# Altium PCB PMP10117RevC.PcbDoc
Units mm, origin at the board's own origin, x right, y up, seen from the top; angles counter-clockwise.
Board outline 44.45 x 78.74 mm, 4 copper layers (Top Layer, Inner Layer 1, Inner Layer 2, Bottom Layer), stack 2.062 mm thick; 56 components, 27 nets, 138 pads, 110 vias.
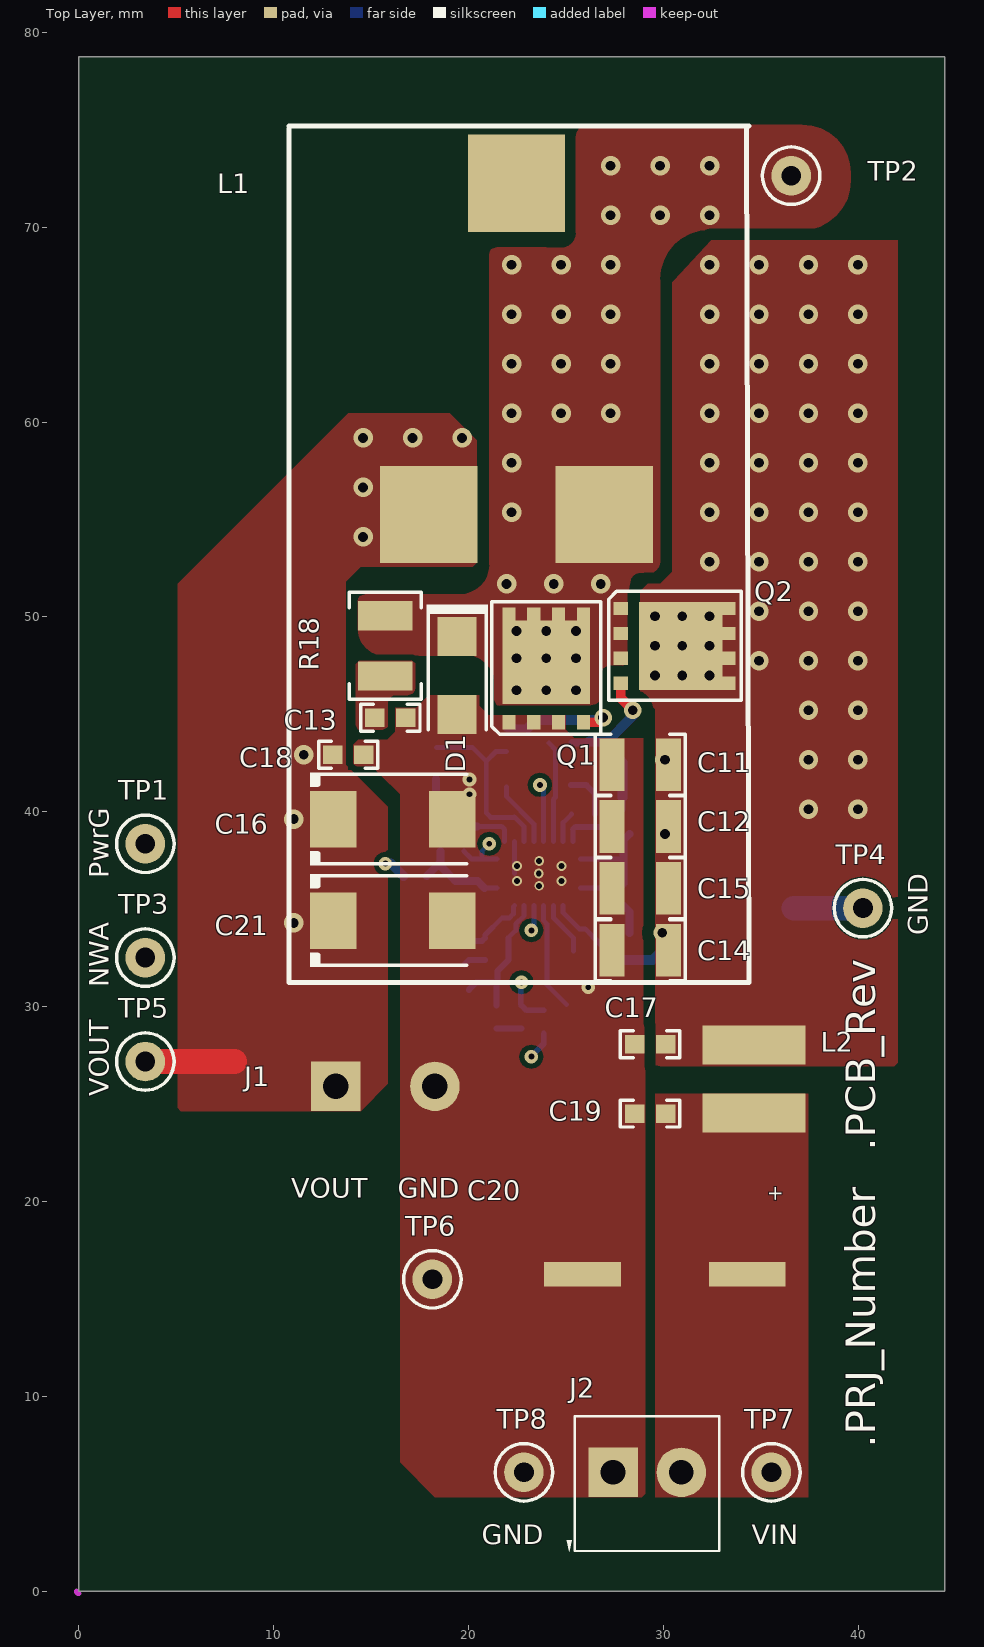
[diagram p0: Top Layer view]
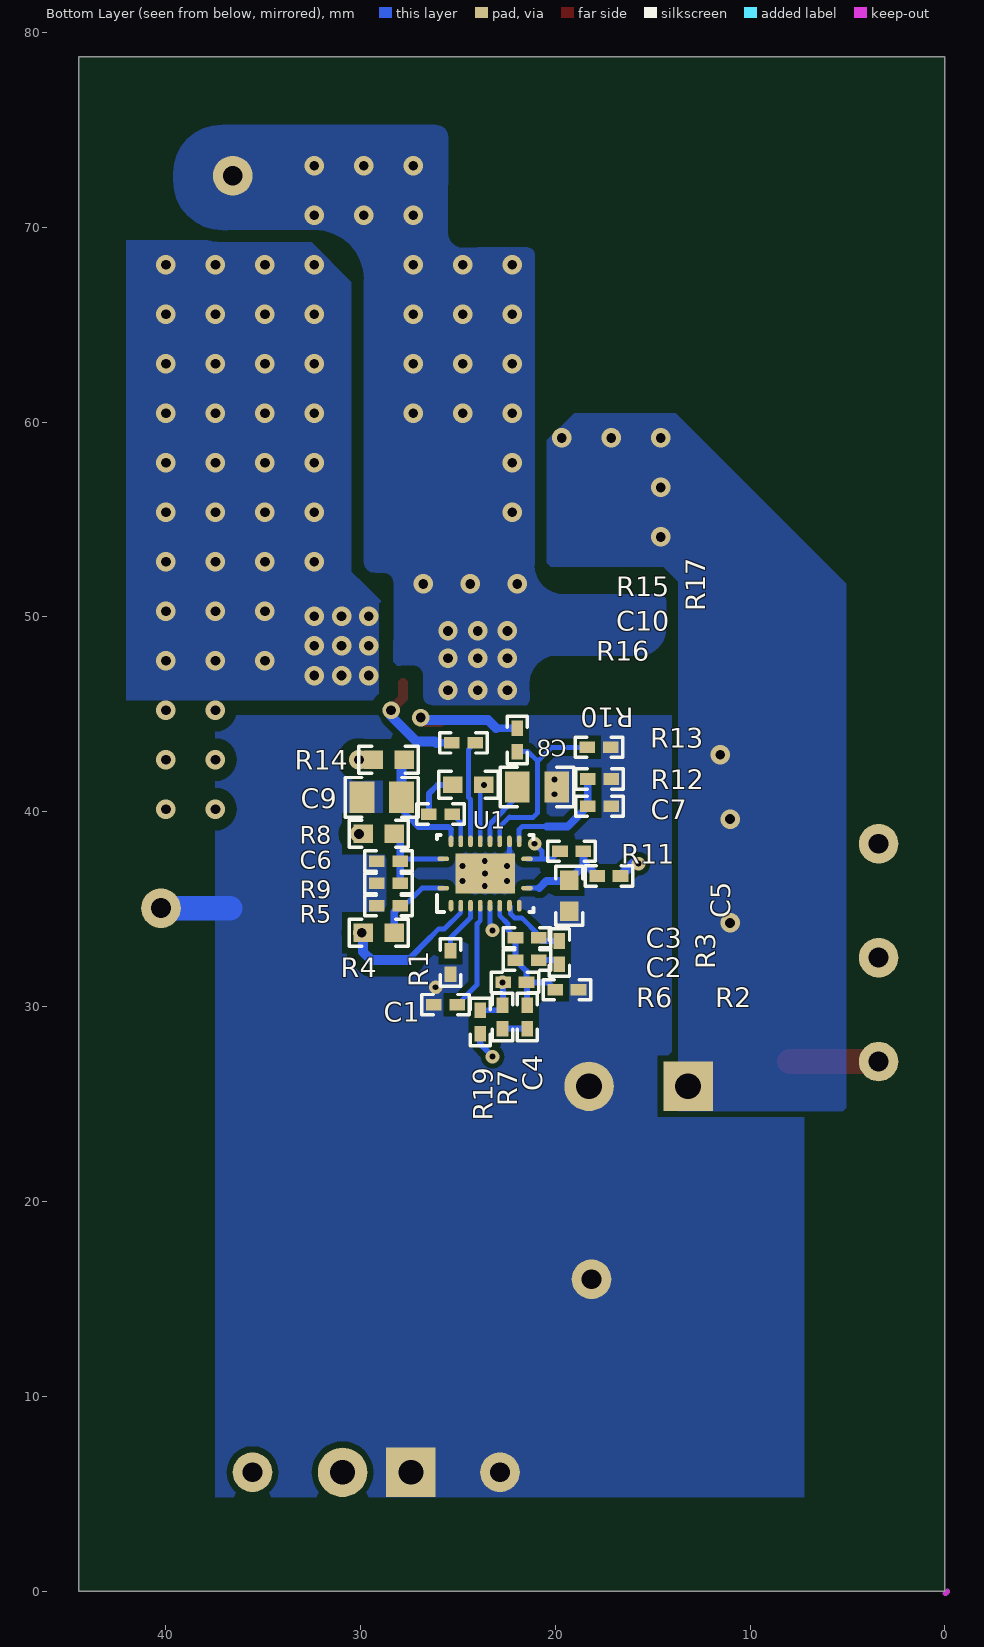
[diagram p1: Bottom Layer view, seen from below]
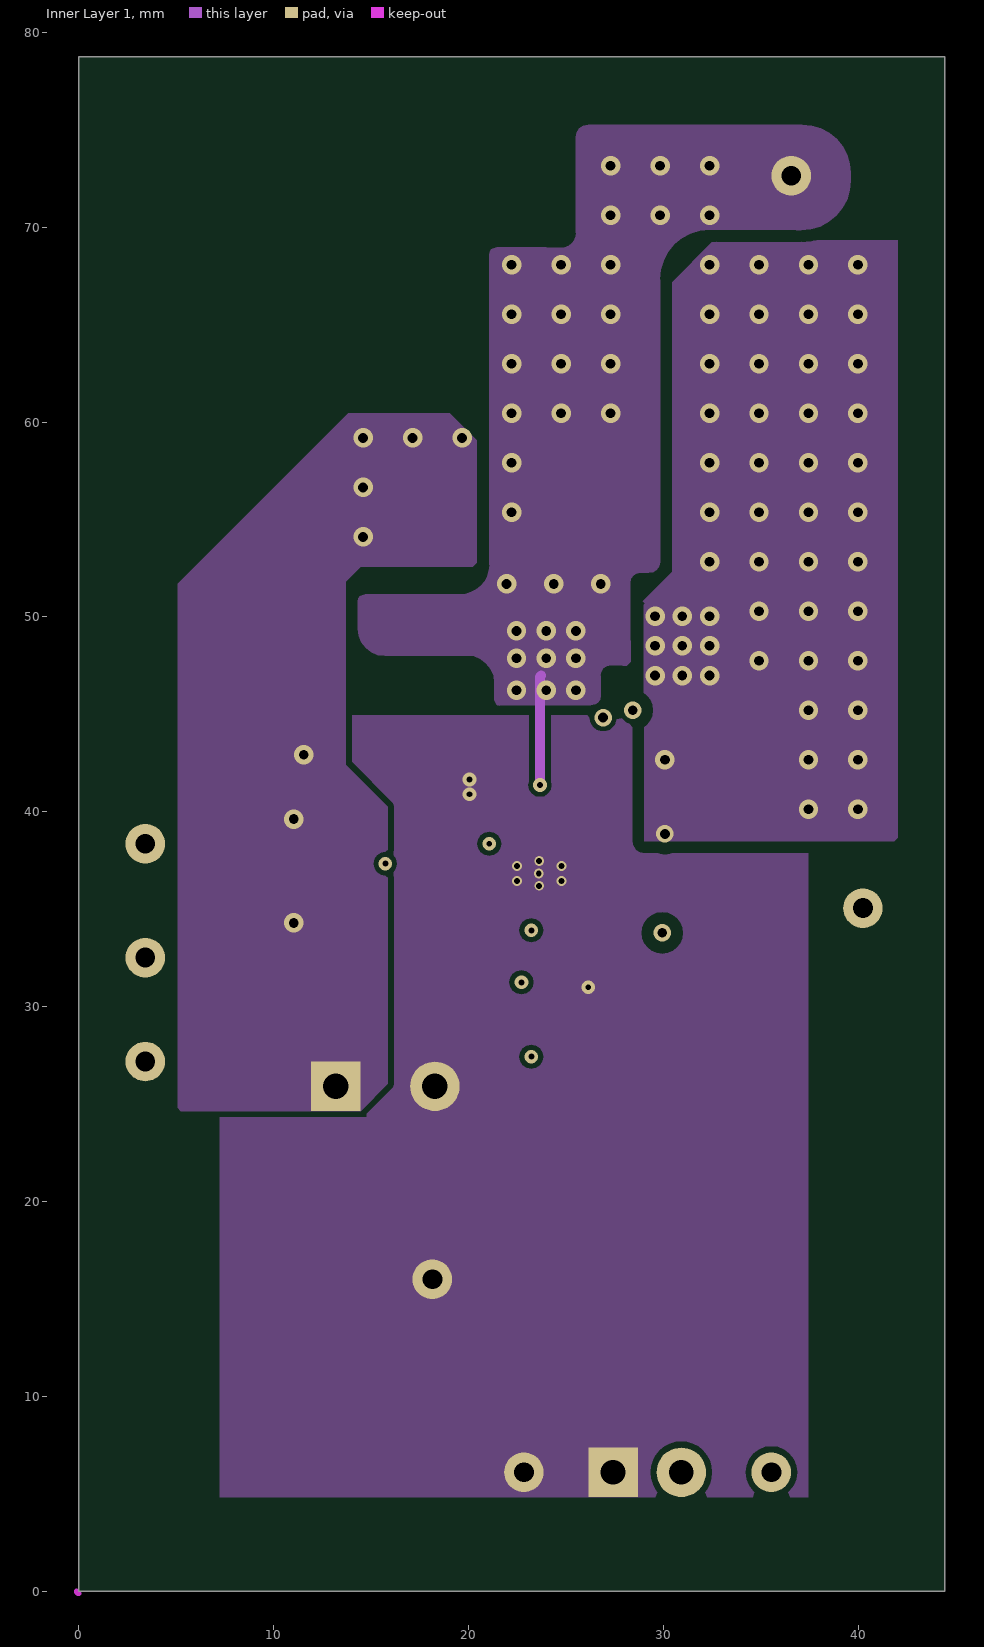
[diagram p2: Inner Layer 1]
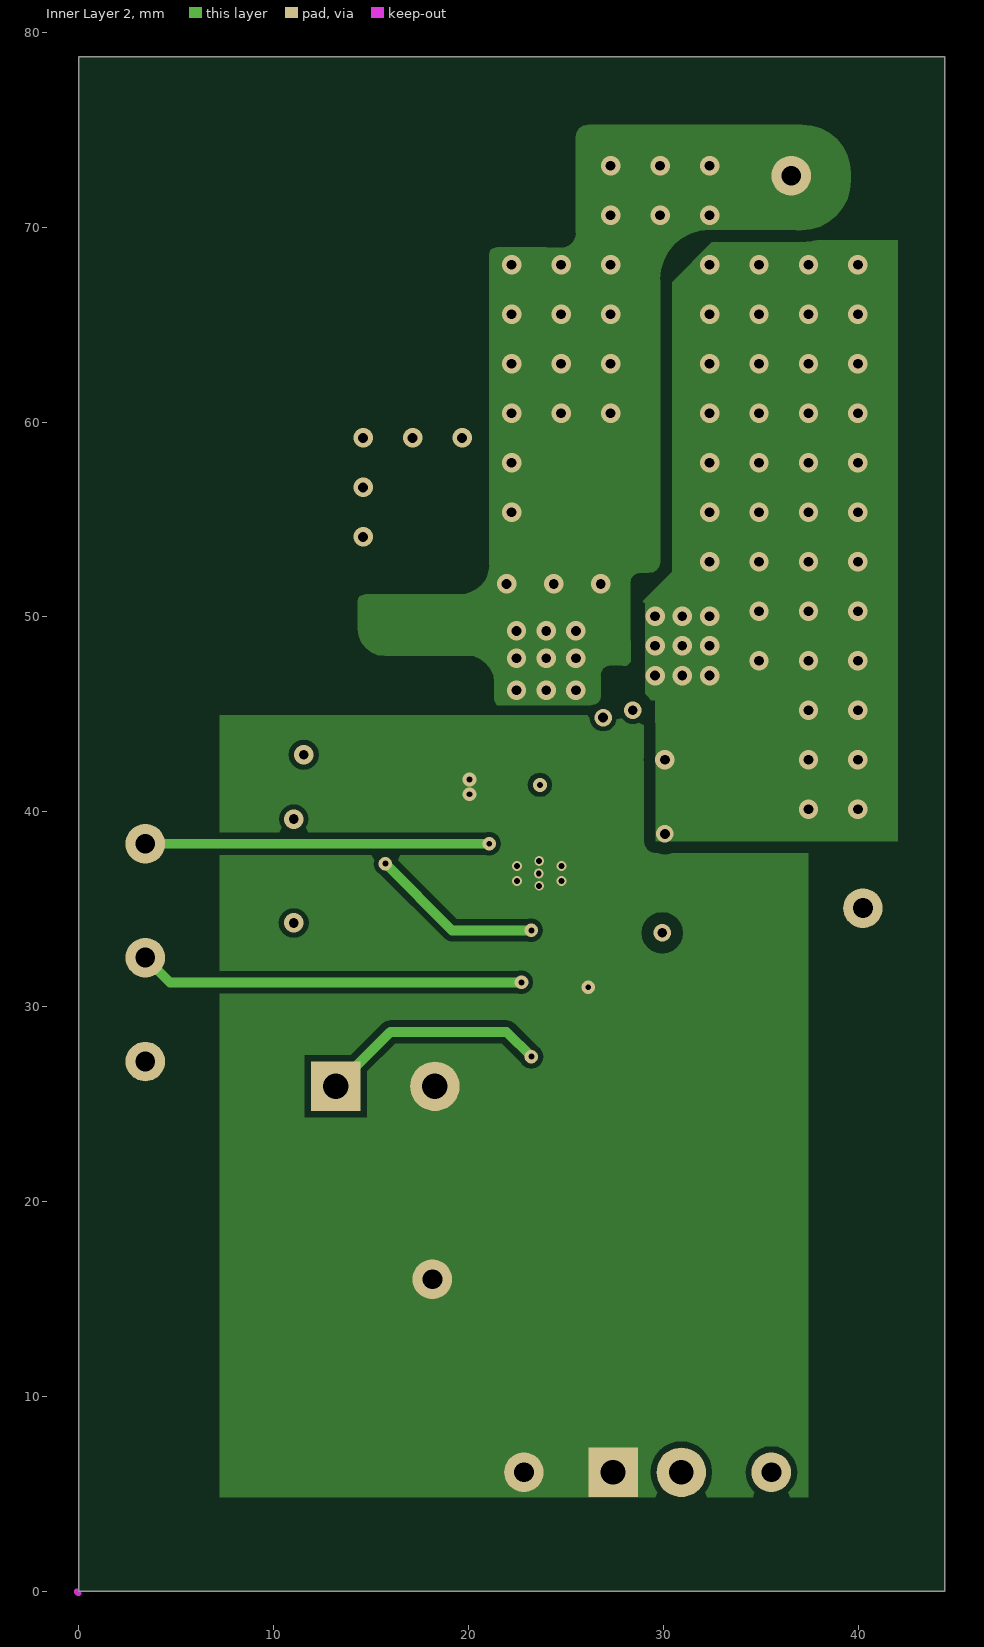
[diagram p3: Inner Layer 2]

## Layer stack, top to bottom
Top Solder: solder mask 0.0102, Solder Resist, Dk 3.5
Top Layer: signal copper 0.07
Dielectric1: core 1.5037, FR-4, Dk 4.8
Inner Layer 1: signal copper 0.036
Dielectric 2: prepreg 0.127, Dk 4.2
Inner Layer 2: signal copper 0.036
Dielectric 3: core 0.254, Dk 4.2
Bottom Layer: signal copper 0.0356
Bottom Solder: solder mask 0.0102, Solder Resist, Dk 3.5

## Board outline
0,0 0,78.74 44.45,78.74 44.45,0

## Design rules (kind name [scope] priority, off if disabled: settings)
AcuteAngle [All] p1: minimum=4.50000000000000E+0001 checktracksonly=FALSE
AssemblyTestPointUsage [All] p1: valid=2
Clearance Clearance_vin [InNet('NetC11_1')] p1: gap=0.6
Clearance Clearance_Keepouts [((IsTrack Or IsArc) And Not InPoly) And IsFree and IsKeepOut vs ((IsTrack Or IsArc) And Not InPoly) And IsFree and IsKeepOut] p2: gap=0
Clearance Clearance_BoardEdge_MountingHoles [OnCopper and InComponentClass('Mounting Holes') vs IsKeepOut] p3: gap=1.016
Clearance Clearance_BoardEdge_Poly [OnCopper and InPoly vs IsKeepOut] p4: gap=0.635
Clearance Clearance_BoardEdge [OnCopper and Not InComponentClass('Logo') and not InComponentClass('FiducialMark') and not InRegion(1000,500,4000,800) and Not IsKeepout vs IsKeepOut] p5: gap=1.5
Clearance Clearance_Poly [InPolygon] p6: gap=0.32 except(0.254: Via-Poly)
Clearance [All] p7: gap=0.32 except(0.2: Track-SMDPad Track-Track)
ComponentClearance ComponentClearance_MountingHoles_FiducialMarks [InComponentClass('Mounting Holes') vs InComponentClass('FiducialMark')] p1: gap=1.27 collisioncheckmode=3 verticalgap=0.254 showdistances=FALSE
ComponentClearance ComponentClearance_Shunt [InComponentClass('Header') vs InComponentClass('Shunt')] p2: gap=0 collisioncheckmode=3 verticalgap=0 showdistances=FALSE
ComponentClearance ComponentClearance_Logo [InComponentClass('Logo')] p3: gap=1.27 collisioncheckmode=3 verticalgap=0.254 showdistances=FALSE
ComponentClearance ComponentClearance_ScrewToNut [(HasFootprint('NY PMS 440 0025 PH')) vs (HasFootprint('Keystone_1902C'))] p4: gap=0.127 collisioncheckmode=3 verticalgap=0.254 showdistances=FALSE
ComponentClearance ComponentClearance_MountingHoles [InComponentClass('Mounting Holes')] p5: gap=6.35 collisioncheckmode=3 verticalgap=2540 showdistances=FALSE
ComponentClearance ComponentClearance_SmallPassives [HasFootprint('0201*') or HasFootprint('0402*') or HasFootprint('0508') or HasFootprint('0603*') or HasFootprint('0612') or HasFootprint('0805*') or HasFootprint('0815*') or HasFootprint('0830*') or HasFootprint('1206*') or HasFootprint('1210*') or HasFootprint('1808*') or HasFootprint('1812*') or HasFootprint('1825*') or HasFootprint('2010*') or HasFootprint('2220*') or HasFootprint('2225*') or HasFootprint('2512*') or HasFootprint('2728*') or HasFootprint('3518*') vs HasFootprint('0201*') or HasFootprint('0402*') or HasFootprint('0508') or HasFootprint('0603*') or HasFootprint('0612') or HasFootprint('0805*') or HasFootprint('0815*') or HasFootprint('0830*') or HasFootprint('1206*') or HasFootprint('1210*') or HasFootprint('1808*') or HasFootprint('1812*') or HasFootprint('1825*') or HasFootprint('2010*') or HasFootprint('2220*') or HasFootprint('2225*') or HasFootprint('2512*') or HasFootprint('2728*') or HasFootprint('3518*')] p6: gap=0.254 collisioncheckmode=3 verticalgap=0.254 showdistances=FALSE
ComponentClearance ComponentClearance_THtoSMT [IsThruComponent vs IsSMTComponent] p7: gap=1.016 collisioncheckmode=3 verticalgap=0.762 showdistances=FALSE
ComponentClearance ComponentClearance_THtoTH [IsThruComponent vs IsThruComponent] p8: gap=1 collisioncheckmode=3 verticalgap=0.762 showdistances=FALSE
ComponentClearance [All] p9: gap=0.502 collisioncheckmode=3 verticalgap=0.254 showdistances=FALSE
DiffPairsRouting [All] p1: maxlimit=2.54 minlimit=0.254 mostfreqgap=0.254 toplayer_minwidth=0.381 toplayer_maxwidth=0.381 toplayer_prefwidth=0.381 midlayer1_minwidth=0.381 midlayer1_maxwidth=0.381 midlayer1_prefwidth=0.381 midlayer2_minwidth=0.381 midlayer2_maxwidth=0.381 midlayer2_prefwidth=0.381 bottomlayer_minwidth=0.381 bottomlayer_maxwidth=0.381 bottomlayer_prefwidth=0.381 maxuncoupledlength=25.4
FabricationTestPointUsage TestPointUsage [All] p1: valid=2 allowmultiple=FALSE
FabricationTestpoint Testpoint [All] p1: side=3 testpointundercomponent=TRUE minsize=1.016 maxsize=2.54 preferedsize=1.524 minholesize=0 maxholesize=1.016 preferedholesize=0.813 testpointgrid=0.025 allowsidetop=TRUE allowsidebottom=TRUE usegrid=TRUE gridtolerance=0
FanoutControl Fanout_LCC [IsLCC] p1: bgadir=Out bgaviamode=Centered fanoutstyle=Auto fanoutdirection=Alternating viagrid=0.025 // Fanout_LCC (Default Rule)
FanoutControl Fanout_BGA [IsBGA] p2: bgadir=Out bgaviamode=Centered fanoutstyle=Auto fanoutdirection=Alternating viagrid=0.025 // Fanout_BGA (Default Rule)
FanoutControl Fanout_Default [All] p4: bgadir=Out bgaviamode=Centered fanoutstyle=Auto fanoutdirection=Alternating viagrid=0.025 // Fanout_Default (Default Rule)
FanoutControl Fanout_Small [(CompPinCount < 5)] p5: bgadir=Out bgaviamode=Centered fanoutstyle=Auto fanoutdirection=OutThenIn viagrid=0.025 // Fanout_Small (Default Rule)
HoleSize [All] p1: absolutevalues=TRUE maxlimit=7 minlimit=0.3 maxpercent=80.000 minpercent=20.000
MinimumAnnularRing MinimumAnnularRing_ThermalPadVias [IsVia and InAnyComponent] p1: minimumring=0.15
MinimumAnnularRing [All] p2: minimumring=0.2
MinimumSolderMaskSliver MinimumSolderMaskSliver_Logo [InComponentClass('Logo') vs InComponentClass('Logo')] p1: minsoldermaskwidth=0.018
MinimumSolderMaskSliver [All] p2: minsoldermaskwidth=0.1
PlaneConnect [All] p1: planeconnectstyle=Relief reliefexpansion=0.254 reliefentries=4 reliefconductorwidth=0.254 reliefairgap=0.254
PolygonConnect [All] p1: connectstyle=Direct reliefconductorwidth=0.254 reliefentries=4 polygonreliefangle="90 Angle" airgapwidth=0.254
RoutingVias ThermalPadVias [IsVia and InAnyComponent] p1: holewidth=0.3 width=0.7 viastyle="Through Hole" minholewidth=0.3 minwidth=0.5 maxholewidth=0.5 maxwidth=1
RoutingVias [All] p2: holewidth=0.5 width=0.7 viastyle="Through Hole" minholewidth=0.3 minwidth=0.7 maxholewidth=1.016 maxwidth=1.651
SilkToBoardRegionClearance [Not ((IsComment or IsDesignator) And (Hide <> 'False')) and not InRegion(1000,500,4000,800)] p1:
SilkToSilkClearance SilkToSilkClearance_Pb-FreeLogo [(HasFootprint('Pb-Free_Overlay_Medium') OR HasFootprint('Pb-Free_Overlay_Small')) vs (HasFootprint('Pb-Free_Overlay_Medium') OR HasFootprint('Pb-Free_Overlay_Small'))] p1: silktosilkclearance=0
SilkToSilkClearance [All] p2: silktosilkclearance=0.127
SilkToSolderMaskClearance "Silk to Solder Mask Opening" [All] p1: minsilkscreentomaskgap=0.025 clearancetoexposedcopper=FALSE
SolderMaskExpansion [All] p1: expansion=0.05
UnpouredPolygon [All] p1: allowunpoured=FALSE
Width [All] p1: maxlimit=2.54 minlimit=0.152 preferedwidth=0.254 checkconnectedcopper=TRUE
14 further rules are at their usual default settings.

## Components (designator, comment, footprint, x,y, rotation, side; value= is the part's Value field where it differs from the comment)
C1 "GRM155R71C104KA88D" 0402 25.634,30.099 r0 bottom
C2 "GRM155R71C153KA01D" 0402 21.443,32.385 r180 bottom
C3 "GRM155R71H221KA01D" 0402 21.443,33.528 r180 bottom
C4 "GRM155R71C103KA01D" 0402 21.443,29.464 r90 bottom
C5 "GRM188R71C105KA12D" 0603#1 19.284,35.687 r270 bottom
C6 "GRM155R71C102KA01D" 0402 28.555,37.465 r0 bottom
C7 "GRM155R71C102KA01D" 0402 17.733,40.278 r180 bottom
C8 "GRM21BR71C475KA73L" 0805_HV 20.935,41.275 r180 bottom
C9 "GRM21BR72A474KA73L" 0805_HV 28.909,40.74 r0 bottom
C10 "GRM188R72A104KA35D" 0603#2 24.464,41.375 r180 bottom
C11 "GRM32ER72A225KA35L" 1210 28.809,42.418 r180 top
C12 "GRM32ER72A225KA35L" 1210 28.809,39.243 r180 top
C13 "GRM188R72A102KA01D" 0603#1 15.982,44.831 r0 top
C14 "GRM32ER72A225KA35L" 1210 28.809,32.893 r180 top
C15 "GRM32ER72A225KA35L" 1210 28.809,36.068 r180 top
C16 "6TPF470MAH" CAPSMT_6_D3L 16.109,39.624 r0 top
C17 "GRM188R72A104KA35D" 0603#1 29.317,28.067 r180 top
C18 "GRM188R71A225KE15D" 0603#1 13.823,42.926 r0 top
C19 "GRM188R72A104KA35D" 0603#1 29.317,24.511 r180 top
C20 "EEEFK1J101P" CAP_EEVFK_SIZE_G 30.079,16.256 r270 top
C21 "6TPF470MAH" CAPSMT_6_D3L 16.109,34.417 r0 top
D1 "B360A-13-F" SMA 19.411,46.99 r270 top
J1 "TBLK_15A_2X5.1MM" TB_2X5.1MM 13.188,25.908 r0 top
J2 "ED555/2DS" TERM_BLK_ED555-2DS 27.412,6.096 r0 top
L1 "7443632200" IND_WE21.5X21.8MM-3P 22.459,63.754 r0 top
L2 "74408943010" WE-SPC-4838 34.651,26.289 r270 top
Q1 "CSD18531Q5A" TRANS_NexFET_Q5A 23.983,47.371 r90 top
Q2 "CSD18537NQ5A" TRANS_NexFET_Q5A 30.587,48.514 r0 top
R1 "CRCW0402100KFKED" 0402 25.38,32.258 r90 bottom
R2 "CRCW04021K33FKED" 0402 19.411,30.861 r180 bottom
R3 "CRCW04027K50FKED" 0402 19.792,32.766 r270 bottom
R4 "CRCW06031M00FKEA" 0603#1 29.063,33.782 r0 bottom
R5 "CRCW0402100KFKED" 0402 28.555,35.179 r180 bottom
R6 "CRCW040210K0FKED" 0402 22.078,31.242 r180 bottom
R7 "CRCW0402160RJNED" 0402 22.713,29.464 r90 bottom
R8 "CRCW06031M00FKEA" 0603#1 29.063,38.862 r0 bottom
R9 "CRCW040220K0FKED" 0402 28.555,36.322 r180 bottom
R10 "CRCW040210K0FKED" 0402 17.252,36.703 r180 bottom
R11 "CRCW040210K0FKED" 0402 19.157,37.973 r180 bottom
R12 "CRCW04025K11FKED" 0402 17.733,41.675 r180 bottom
R13 "CRCW040210K0FKED" 0402 17.76,43.307 r0 bottom
R14 "CRCW06031R00FKEA" 0603#1 28.555,42.672 r0 bottom
R15 "CRCW04020000Z0ED" 0402 24.718,43.534 r0 bottom
R16 "CRCW04020000Z0ED" 0402 25.888,39.878 r0 bottom
R17 "CRCW04020000Z0ED" 0402 21.951,43.688 r90 bottom
R18 "ERJ-P14J3R3U" 1210M 15.728,48.514 r90 top
R19 "CRCW040249R9FKED" 0402 23.856,29.21 r270 bottom
TP1 "5002" Keystone5002 3.409,38.354 r0 top
TP2 "5002" Keystone5002 36.556,72.644 r0 top
TP3 "5003" Keystone5003 3.409,32.512 r0 top
TP4 "5001" Keystone5001 40.239,35.052 r0 top
TP5 "5000" Keystone5000 3.409,27.178 r0 top
TP6 "5001" Keystone5001 18.141,16.002 r0 top
TP7 "5000" Keystone5000 35.54,6.096 r0 top
TP8 "5001" Keystone5001 22.84,6.096 r0 top
U1 "TPS40170RGY" RGY0020A 23.602,36.83 r90 bottom

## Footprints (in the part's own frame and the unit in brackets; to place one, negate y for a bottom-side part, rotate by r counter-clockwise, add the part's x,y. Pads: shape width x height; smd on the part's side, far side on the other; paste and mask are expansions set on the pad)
0402 [mm] "0402 from SM-752 data"
  rect 0.8x0.6 smd: 1(-0.6,0) 2(0.6,0)
  silkscreen extent -1.22,-0.52 1.22,0.52, body extent -0.55,-0.3 0.55,0.3, height 0.6
0603#1 [mm] "0603 from SM-752 data"
  rect 1x0.95 smd: 1(-0.8,0) 2(0.8,0)
  silkscreen extent -1.52,-0.69 1.52,0.69, body extent -0.87,-0.47 0.87,0.47, height 0.85
0603#2 [mm] "0603 from SM-752 data"
  rect 1x0.85 smd: 1(-0.8,0) 2(0.8,0)
  silkscreen extent -1.52,-0.69 1.52,0.69, body extent -0.87,-0.47 0.87,0.47, height 0.85
0805_HV [mil] "0805 with 30mil clearance between pads"
  rect 50x63 smd: 1(-40,0) 2(40,0)
  silkscreen extent -74,-40 74,40, body extent -43,-29 43,29, height 43
1210 [mm] "1210 from SM-752 data"
  rect 1.3x2.7 smd: 1(-1.45,0) 2(1.45,0)
  silkscreen extent -2.32,-1.57 2.32,1.57, body extent -1.7,-1.35 1.7,1.35, height 1.35
1210M [mm] "1210 from SM-752 data"
  rect 1.5x2.8 smd: 1(-1.55,0) 2(1.55,0)
  silkscreen extent -2.75,-1.85 2.75,1.85, body extent -1.7,-1.35 1.7,1.35, height 1.35
CAP_EEVFK_SIZE_G [mil]
  rect 50x155 smd: 1(0,166.5) 2(0,-166.5)
CAPSMT_6_D3L [mm] "Panasonic recommended land pattern for size code D3L"
  rect 2.4x2.9 smd: 1(-3.05,0) 2(3.05,0)
  silkscreen extent -4.25,-2.39 3.8,2.39, body extent -3.8,-2.3 3.8,2.3, height 2.9
IND_WE21.5X21.8MM-3P [mm]
  rect 5x5 smd: 1(-4.5,-8.5) 2(4.5,-8.5) 3(0,8.5)
Keystone5000 [mil] "For Keystone 500x miniature loop terminals"
  round 80 hole 40: 1(0,0)
  silkscreen extent -58,-58 58,58, body extent -49,-49 49,49, height 182
Keystone5001 [mil] "For Keystone 500x miniature loop terminals"
  round 80 hole 40: 1(0,0)
  silkscreen extent -58,-58 58,58, body extent -49,-49 49,49, height 182
Keystone5002 [mil] "For Keystone 500x miniature loop terminals"
  round 80 hole 40: 1(0,0)
  silkscreen extent -58,-58 58,58, body extent -49,-49 49,49, height 182
Keystone5003 [mil] "For Keystone 500x miniature loop terminals"
  round 80 hole 40: 1(0,0)
  silkscreen extent -58,-58 58,58, body extent -49,-49 49,49, height 182
RGY0020A [mm] "QFN, 20-Leads, Body 4.5x3.5mm, Pitch 0.5mm, Thermal Pad 3.05x2.05mm, TI Recommended"
  oval 0.24x0.6 smd: 1(-0.75,2.15) 10(-0.75,-2.15) 11(0.75,-2.15) 20(0.75,2.15)
  oval 0.6x0.24 smd: 2(-1.65,1.75) 3(-1.65,1.25) 4(-1.65,0.75) 5(-1.65,0.25) 6(-1.65,-0.25) 7(-1.65,-0.75) 8(-1.65,-1.25) 9(-1.65,-1.75) 12(1.65,-1.75) 13(1.65,-1.25) 14(1.65,-0.75) 15(1.65,-0.25) 16(1.65,0.25) 17(1.65,0.75) 18(1.65,1.25) 19(1.65,1.75)
  rect 2.05x3.05 smd paste-1.025: 21(0,0)
  silkscreen extent -1.97,-2.47 1.97,2.47, body extent -1.83,-2.33 1.83,2.32, height 1.01
SMA [mm] "Molded Diode, 2-Leads, Body 4.3x2.6mm, IPC Medium Density, based on OnSemi component dimensions and land pattern"
  rect 2x2 smd: 1(-2,0) 2(2,0)
  silkscreen extent -3.66,-1.57 2.79,1.57, body extent -2.6,-1.3 2.6,1.3, height 2.42
TB_2X5.1MM [mil]
  rect 100x100 hole 52: 1(0,0)
  round 100 hole 52: 2(200,0)
TERM_BLK_ED555-2DS [mil]
  rect 100x100 hole 50: 1(0,0)
  round 100 hole 50: 2(138,0)
  silkscreen extent -93,-161 215,113, body extent -69,-150 207,106, height 323
TRANS_NexFET_Q5A [mm] "TI recommended land pattern (nominal) M0139-01"
  rect 0.75x0.675 smd paste-0.1 mask+0.051: 1(-2.776,1.917) 2(-2.776,0.639) 3(-2.776,-0.639) 4(-2.776,-1.917)
  rect 0.655x0.675 smd paste-0.1 mask+0.051: 5(2.776,-1.917) 6(2.776,-0.639) 7(2.776,0.639) 8(2.776,1.917)
  rect 4.295x4.51 smd paste-2.2 mask+0.051: 9(0.301,0)
  silkscreen extent -3.4,-2.8 3.4,2.8, body extent -3.05,-2.5 3.05,2.5, height 1.11
WE-SPC-4838 [mm] "WURTH"
  rect 2x5.3 smd: 1(-1.75,0) 2(1.75,0)
  body extent -2.55,-2.55 2.55,2.55, height 4.1

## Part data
C1: "CAP, CERM, 0.1 µF, 16 V, +/- 10%, X7R, 0402"
C2: "CAP, CERM, 0.015 µF, 16 V, +/- 10%, X7R, 0402"
C3: "CAP, CERM, 220 pF, 50 V, +/- 10%, X7R, 0402"
C4: "CAP, CERM, 0.01 µF, 16 V, +/- 10%, X7R, 0402"
C5: "CAP, CERM, 1 µF, 16 V, +/- 10%, X7R, 0603"
C6 C7: "CAP, CERM, 1000 pF, 16 V, +/- 10%, X7R, 0402"
C8: "CAP, CERM, 4.7 µF, 16 V, +/- 10%, X7R, 0805"
C9: "CAP, CERM, 0.47 µF, 100 V, +/- 10%, X7R, 0805"
C10 C17 C19: "CAP, CERM, 0.1 µF, 100 V, +/- 10%, X7R, 0603"
C11 C12 C14 C15: "CAP, CERM, 2.2 µF, 100 V, +/- 10%, X7R, 1210"
C13: "CAP, CERM, 1000 pF, 100 V, +/- 10%, X7R, 0603"
C16 C21: library part CAP_OSCON_SM-D, "Capacitor, POSCAP, 6.3V, 20%, 10milliOhms, 4.4Arms"
C18: "CAP, CERM, 2.2 µF, 10 V, +/- 10%, X7R, 0603"
C20: library part CAP_EEEFK1-CODE_G, "Capacitor, Aluminum, 63V, 100uF ±20%, 10mm x 10.2mm"
D1: "Diode, Schottky, 60V, 3A, SMA"
J1: "Terminal Block, 2-pin, 15-A, 5.1mm"
J2: "Terminal Block, 6A, 3.5mm Pitch, 2-Pos, TH"
L1: library part IND_7443634700, "Inductor, Power Coke, 10.7mOhm, 12Adc"
L2: "Inductor, Shielded Drum Core, Ferrite, 1uH, 3.3A, 0.019 ohm, SMD"
Q1: "MOSFET, N-CH, 60V, 19A, SON 5x6mm"
Q2: "MOSFET, N-CH, 60V, 50A, SON 5x6mm"
R1 R5: "RES, 100 k, 1%, 0.063 W, 0402"
R2: "RES, 1.33 k, 1%, 0.063 W, 0402"
R3: "RES, 7.50 k, 1%, 0.063 W, 0402"
R4 R8: "RES, 1.00 M, 1%, 0.1 W, 0603"
R6 R10 R11 R13: "RES, 10.0 k, 1%, 0.063 W, 0402"
R7: "RES, 160, 5%, 0.063 W, 0402"
R9: "RES, 20.0 k, 1%, 0.063 W, 0402"
R12: "RES, 5.11 k, 1%, 0.063 W, 0402"
R14: "RES, 1.00, 1%, 0.1 W, 0603"
R15 R16 R17: "RES, 0, 5%, 0.063 W, 0402"
R18: "RES, 3.3, 5%, 0.5 W, 1210"
R19: "RES, 49.9, 1%, 0.063 W, 0402"
TP1 TP2: "Test Point, Miniature, White, TH"
TP3: "Test Point, Miniature, Orange, TH"
TP4 TP6 TP8: "Test Point, Miniature, Black, TH"
TP5 TP7: "Test Point, Miniature, Red, TH"
U1: "4.5-v to 60-v wide-input synchronous PWM buck controller, RGY0020A"

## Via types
v1: diameter 1, hole 0.5, Top Layer to Bottom Layer, tented both sides, 90 vias
v2: diameter 0.7, hole 0.3, Top Layer to Bottom Layer, tented both sides, 6 vias
v3: diameter 0.9, hole 0.5, Top Layer to Bottom Layer, tented both sides, 4 vias
v4: diameter 0.5, hole 0.3, Top Layer to Bottom Layer, 4 vias
v5: diameter 0.5, hole 0.3, Top Layer to Bottom Layer, tented both sides, 3 vias
v6: diameter 0.7, hole 0.3, Top Layer to Bottom Layer, tented top, 3 vias

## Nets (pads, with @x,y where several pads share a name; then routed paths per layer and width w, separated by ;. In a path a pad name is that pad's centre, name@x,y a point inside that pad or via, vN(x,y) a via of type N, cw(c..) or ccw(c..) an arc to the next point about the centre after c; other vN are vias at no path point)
GND: C1.2 C5.2 C6.2 C7.2 C8.2 C9.2 C11.2 C12.2 C13.2 C14.2 C15.2 C16.2 C17.2 C18.2 C19.2 C20.2 C21.2 D1.2 J1.2 J2.1 Q1.1 Q1.2 Q1.3 R1.1 R2.2 R5.1 R9.1 R12.2 R13.1 TP4.1 TP6.1 TP8.1 U1.9 U1.13 U1.21 | length 5.2
  Bottom Layer w0.254: U1.21@22.352,36.83 U1.13
  Bottom Layer w1.27: 36.683,35.052 TP4.1
  other v2: 26.142,30.988
  other v4: 23.622,36.195 22.479,36.449 24.765,37.211 23.622,37.465
  other v5: 24.765,36.449 23.602,36.83 22.479,37.211
  other v6: 20.046,40.894 20.046,41.656
NetC1_1: C1.1 U1.5 | length 5.6
  Bottom Layer w0.254: U1.5 23.852,34.405 24.018,34.239 24.018,31.115 C1.1
NetC2_1: C2.1 C3.1 C4.2 R2.1 R6.2 U1.7 | length 7.3
  Bottom Layer w0.254: C3.1 22.424,33.909 22.424,34.239 22.852,34.667 U1.7
  Bottom Layer w0.305: R2.1 20.392,31.242 R6.2 ; C4.2 21.443,31.207 R6.2 ; C3.1 C2.1 21.478,31.82 R6.2
NetC2_2: C2.2 R3.2 | length 1.1
  Bottom Layer w0.305: R3.2 20.011,32.385 C2.2
NetC3_2: C3.2 R3.1 U1.8 | length 3.6
  Bottom Layer w0.254: C3.2 20.843,33.671 21.725,34.553 22.096,34.553 22.299,34.756 22.299,35.127 U1.8
  Bottom Layer w0.305: R3.1 20.681,33.366 C3.2
NetC4_1: C4.1 R7.1 | length 1.3
  Bottom Layer w0.305: C4.1 R7.1
NetC5_1: C5.1 R10.1 R11.2 U1.10 | length 5.1
  Bottom Layer w0.254: 20.82,36.08 U1.10
  Bottom Layer w0.4: R10.1 18.557,37.408 ; R11.2 18.557,37.408 ; 20.82,36.08 20.451,36.449 19.322,36.449 C5.1 18.557,37.214 18.557,37.408
NetC6_1: C6.1 R8.1 R9.2 U1.20 | length 4.9
  Bottom Layer w0.254: U1.20 C6.1@27.84,37.58
  Bottom Layer w0.305: C6.1@27.84,37.58 C6.1
  Bottom Layer w0.4: R9.2 C6.1 27.955,38.554 R8.1
NetC7_1: C7.1 R12.1 U1.12 | length 6
  Bottom Layer w0.254: 20.427,39.243 21.697,39.243 21.852,39.088 U1.12
  Bottom Layer w0.4: R12.1 C7.1 19.368,39.243 20.427,39.243
NetC8_1: C8.1 U1.15 | length 3.4
  Bottom Layer w0.254: C8.1 21.951,40.774 23.352,39.373 U1.15
NetC9_1: C9.1 R14.1 U1.19 | length 6.2
  Bottom Layer w0.254: U1.19 25.352,39.088
  Bottom Layer w0.305: 25.352,39.088 25.49,39.226 27.034,39.226 27.24,39.432 27.24,39.452 27.893,40.105 C9.1
  Bottom Layer w0.508: R14.1 27.893,42.534 C9.1
NetC10_1: C10.1 R16.2 | length 2.5
  Bottom Layer w0.305: C10.1 26.042,41.375 26.488,40.929 R16.2
NetC10_2: C10.2 D1.1 L1.2 Q1.5 Q1.6 Q1.7 Q1.8 Q1.9 Q2.1 Q2.2 Q2.3 R18.2 TP2.1 U1.16 | length 8.6
  Inner Layer 1 w0.508: v6(23.664,41.375) 23.664,46.925 23.729,46.99
  Bottom Layer w0.254: v6(23.664,41.375) 23.852,41.187 U1.16
  other v1: 22.459,46.228 23.983,46.228 25.507,46.228 22.459,47.879 23.983,47.879 25.507,47.879 22.459,49.276 23.983,49.276 25.507,49.276 21.951,51.689 24.364,51.689 26.777,51.689 22.205,55.372 22.205,57.912 22.205,60.452 24.745,60.452 27.285,60.452 22.205,62.992 24.745,62.992 27.285,62.992 22.205,65.532 24.745,65.532 27.285,65.532 22.205,68.072 24.745,68.072 27.285,68.072 27.285,70.612 29.825,70.612 32.365,70.612 27.285,73.152 29.825,73.152 32.365,73.152
NetC11_1: C11.1 C12.1 C14.1 C15.1 C17.1 L2.1 Q2.5 Q2.6 Q2.7 Q2.8 Q2.9 R4.2 R8.2 R14.2 U1.3 | length 7.5
  Bottom Layer w0.254: U1.3 24.852,34.818 25.685,33.985 25.981,33.985 26.407,33.559
  Bottom Layer w0.305: 26.407,33.559 27.581,32.385
  Bottom Layer w0.508: 27.581,32.385 29.444,32.385 29.863,32.804 R4.2
  other v1: 37.445,40.132 39.985,40.132 30.079,42.672 37.445,42.672 39.985,42.672 37.445,45.212 39.985,45.212 29.571,46.99 30.968,46.99 32.365,46.99 34.905,47.752 37.445,47.752 39.985,47.752 29.571,48.514 30.968,48.514 32.365,48.514 29.571,50.038 30.968,50.038 32.365,50.038 34.905,50.292 37.445,50.292 39.985,50.292 32.365,52.832 34.905,52.832 37.445,52.832 39.985,52.832 32.365,55.372 34.905,55.372 37.445,55.372 39.985,55.372 32.365,57.912 34.905,57.912 37.445,57.912 39.985,57.912 32.365,60.452 34.905,60.452 37.445,60.452 39.985,60.452 32.365,62.992 34.905,62.992 37.445,62.992 39.985,62.992 32.365,65.532 34.905,65.532 37.445,65.532 39.985,65.532 32.365,68.072 34.905,68.072 37.445,68.072 39.985,68.072
  other v3: 29.938,33.782 30.079,38.862
NetC13_1: C13.1 R18.1
NetC16_1: C16.1 C18.1 C21.1 J1.1 L1.1 R19.2 TP5.1 | length 17.7
  Top Layer w1.27: TP5.1 7.981,27.178
  Inner Layer 2 w0.508: J1.1 15.982,28.702 21.951,28.702 v2(23.221,27.432)
  Bottom Layer w0.305: v2(23.221,27.432) 23.221,27.452 23.856,28.087 R19.2
  other v1: 11.029,34.29 11.029,39.624 11.537,42.926 14.585,54.102 14.585,56.642 14.585,59.182 17.125,59.182 19.665,59.182
NetC19_1: C19.1 C20.1 J2.2 L2.2 TP7.1
NetQ1_4: Q1.4 R17.2 | length 6.3
  Top Layer w0.508: Q1.4 26.668,44.595 v3(26.904,44.831)
  Bottom Layer w0.38: R17.2 23.037,44.288
  Bottom Layer w0.508: 23.037,44.288 23.453,44.704 26.777,44.704 v3(26.904,44.831)
NetQ2_4: Q2.4 R15.2 | length 5.6
  Top Layer w0.508: Q2.4 27.811,45.829 v3(28.428,45.212)
  Bottom Layer w0.38: R15.2 26.111,43.534
  Bottom Layer w0.508: 26.111,43.534 26.178,43.601 27.122,43.601 28.428,44.907 v3(28.428,45.212)
NetR1_2: R1.2 U1.4 | length 2.7
  Bottom Layer w0.254: 24.352,34.556 U1.4 ; 24.364,34.544 25.38,33.528 R1.2
NetR4_1: R4.1 R5.2 U1.1 | length 4.1
  Bottom Layer w0.254: U1.1 26.843,36.08 27.744,35.179 R5.2
  Bottom Layer w0.4: R5.2 28.263,34.871 R4.1
NetR6_1: R6.1 R7.2 R19.1 TP3.1 | length 22.3
  Inner Layer 2 w0.508: TP3.1 4.679,31.242 v2(22.713,31.242)
  Bottom Layer w0.305: R6.1 22.678,30.099 R7.2 22.967,29.81 R19.1
NetR10_2: R10.2 U1.6 | length 11.4
  Inner Layer 2 w0.508: v2(15.728,37.338) 19.157,33.909 v2(23.221,33.909)
  Bottom Layer w0.254: v2(23.221,33.909) 23.352,34.04 U1.6
  Bottom Layer w0.508: v2(15.728,37.338) 16.017,37.338 R10.2
NetR11_1: R11.1 TP1.1 U1.11 | length 20.8
  Inner Layer 2 w0.508: TP1.1@3.409,37.973 TP1.1@3.663,38.227 ; TP1.1 v2(21.062,38.354)
  Bottom Layer w0.254: R11.1 20.15,37.58 20.681,37.58 ; v2(21.062,38.354) 20.681,37.973 20.681,37.58 ; U1.11 20.681,37.58
NetR13_2: R13.2 R17.1 U1.14 | length 9.8
  Bottom Layer w0.254: R13.2 20.188,43.307 20.906,42.589 ; R17.1 21.405,43.088 20.906,42.589 ; U1.14 22.852,39.231 22.344,39.739 22.319,39.714 21.131,39.714 20.906,39.939 20.906,42.589
NetR15_1: R15.1 U1.17 | length 5.2
  Bottom Layer w0.254: R15.1 24.464,43.188 24.464,40.738 24.352,40.626 U1.17
NetR16_1: R16.1 U1.18 | length 1.6
  Bottom Layer w0.254: U1.18 24.852,39.442 R16.1
pads on no net: L1.3 U1.2

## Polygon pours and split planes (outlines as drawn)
NetC13_1 on Top Layer "Top Layer-No Net 1" (solid, remove dead copper, pour order 22): 14.331,47.752 17.125,47.752 cw(c17.125,47.625) 17.252,47.625 17.252,46.355 cw(c16.871,46.355) 16.871,45.974 16.273,45.974 ccw(c16.273,45.556) 15.855,45.556 15.855,44.45 cw(c15.601,44.45) 15.601,44.196 14.458,44.196 cw(c14.458,44.45) 14.204,44.45 14.204,47.578 cw(c14.378,47.578) 14.378,47.752
NetC16_1 on Top Layer "Top Layer-vout" (solid, remove dead copper, pour order 27): 19.03,60.452 13.823,60.452 5.06,51.689 5.06,24.638 14.458,24.638 15.855,26.035 15.855,40.259 13.696,42.418 13.696,44.45 13.696,51.816 14.458,52.578 20.3,52.578 20.427,52.705 20.427,59.055
NetC10_2 on Top Layer "Top Layer-No Net 2" (solid, remove dead copper, pour order 35): 28.301,47.625 cw(c28.174,47.625) 28.174,47.498 27.92,47.498 27.286,47.498 ccw(c27.286,46.99) 26.778,46.99 26.778,45.953 cw(c26.281,45.953) 26.281,45.456 21.58,45.456 cw(c21.58,45.72) 21.316,45.72 21.316,46.609 ccw(c19.919,46.609) 19.919,48.006 15.775,48.006 15.706,48.006 cw(c15.706,49.391) 14.321,49.391 14.321,50.804 cw(c14.69,50.804) 14.69,51.174 19.567,51.174 ccw(c19.567,52.672) 21.066,52.672 21.066,68.584 cw(c21.443,68.584) 21.443,68.961 23.983,68.961 24.745,68.961 ccw(c24.745,69.723) 25.507,69.723 25.507,74.619 cw(c26.142,74.619) 26.142,75.254 37.121,75.254 cw(c37.121,72.771) 39.604,72.771 39.604,72.39 cw(c37.064,72.39) 37.064,69.85 36.937,69.85 32.365,69.85 ccw(c32.365,67.31) 29.825,67.31 29.825,52.832 cw(c29.247,52.832) 29.247,52.254 28.809,52.254 ccw(c28.809,51.746) 28.301,51.746 28.301,49.911
NetC11_1 on Top Layer "Top Layer-vin2" (solid, remove dead copper, pour order 21): 30.46,52.324 30.46,67.178 30.562,67.28 32.449,69.342 42.017,69.342 42.017,26.924 29.571,26.924 29.571,45.252 28.809,46.014 28.809,51.309 29.189,51.69 29.825,51.69
NetC19_1 on Top Layer "Top Layer-vin" (solid, remove dead copper, pour order 20): 29.571,4.826 37.445,4.826 37.445,25.654 37.445,25.527 29.571,25.527
GND on Top Layer "Top Layer-gnd" (solid, remove dead copper, pour order 31): 24.999,44.958 21.024,44.958 20.897,45.085 20.554,45.428 20.554,45.974 18.014,45.974 17.95,45.974 17.532,45.556 17.315,45.339 16.236,45.339 16.236,44.106 15.818,43.688 14.585,43.688 14.331,43.688 14.077,43.434 14.077,42.324 15.06,42.324 15.474,41.91 16.49,40.894 16.49,39.37 16.49,22.733 16.49,6.604 18.268,4.826 29.063,4.826 29.063,30.48 29.063,43.768 25.427,43.768 25.38,43.815 24.999,44.196
NetC11_1 on Inner Layer 1 "Inner Layer 1-vin2" (solid, remove dead copper, pour order 24): 28.981,50.8 42.017,50.8 42.017,38.481 29.023,38.481
NetC10_2 on Inner Layer 1 "Top Layer-No Net 2" (solid, remove dead copper, pour order 34): 28.301,47.625 cw(c28.174,47.625) 28.174,47.498 27.92,47.498 27.286,47.498 ccw(c27.286,46.99) 26.778,46.99 26.778,45.953 cw(c26.281,45.953) 26.281,45.456 21.58,45.456 cw(c21.58,45.72) 21.316,45.72 21.316,46.609 ccw(c19.919,46.609) 19.919,48.006 15.775,48.006 15.706,48.006 cw(c15.706,49.391) 14.321,49.391 14.321,50.804 cw(c14.69,50.804) 14.69,51.174 19.567,51.174 ccw(c19.567,52.672) 21.066,52.672 21.066,68.584 cw(c21.443,68.584) 21.443,68.961 23.983,68.961 24.745,68.961 ccw(c24.745,69.723) 25.507,69.723 25.507,74.619 cw(c26.142,74.619) 26.142,75.254 37.121,75.254 cw(c37.121,72.771) 39.604,72.771 39.604,72.39 cw(c37.064,72.39) 37.064,69.85 36.937,69.85 32.365,69.85 ccw(c32.365,67.31) 29.825,67.31 29.825,52.832 cw(c29.247,52.832) 29.247,52.254 28.809,52.254 ccw(c28.809,51.746) 28.301,51.746 28.301,49.911
NetC11_1 on Inner Layer 1 "Inner Layer 1-No Net" (solid, remove dead copper, pour order 38): 42.017,45.72 42.017,69.342 32.492,69.342 32.492,69.215 30.46,67.183 30.46,52.324 29.825,51.689 28.936,50.8 29.063,50.673 29.063,45.719
GND on Inner Layer 1 "Bottom Layer-gnd" (solid, remove dead copper, pour order 30): 7.219,44.958 37.445,44.958 37.445,4.826 7.219,4.826
NetC16_1 on Inner Layer 1 "Top Layer-vout" (solid, remove dead copper, pour order 26): 19.03,60.452 13.823,60.452 5.06,51.689 5.06,24.638 14.458,24.638 15.855,26.035 15.855,40.259 13.696,42.418 13.696,44.45 13.696,51.816 14.458,52.578 20.3,52.578 20.427,52.705 20.427,59.055
NetC11_1 on Inner Layer 2 "Inner Layer 1-vin2" (solid, remove dead copper, pour order 23): 29.571,50.8 42.017,50.8 42.017,38.481 29.613,38.481
NetC10_2 on Inner Layer 2 "Top Layer-No Net 2" (solid, remove dead copper, pour order 33): 28.301,47.625 cw(c28.174,47.625) 28.174,47.498 27.92,47.498 27.286,47.498 ccw(c27.286,46.99) 26.778,46.99 26.778,45.953 cw(c26.281,45.953) 26.281,45.456 21.58,45.456 cw(c21.58,45.72) 21.316,45.72 21.316,46.609 ccw(c19.919,46.609) 19.919,48.006 15.775,48.006 15.706,48.006 cw(c15.706,49.391) 14.321,49.391 14.321,50.804 cw(c14.69,50.804) 14.69,51.174 19.567,51.174 ccw(c19.567,52.672) 21.066,52.672 21.066,68.584 cw(c21.443,68.584) 21.443,68.961 23.983,68.961 24.745,68.961 ccw(c24.745,69.723) 25.507,69.723 25.507,74.619 cw(c26.142,74.619) 26.142,75.254 37.121,75.254 cw(c37.121,72.771) 39.604,72.771 39.604,72.39 cw(c37.064,72.39) 37.064,69.85 36.937,69.85 32.365,69.85 ccw(c32.365,67.31) 29.825,67.31 29.825,52.832 cw(c29.247,52.832) 29.247,52.254 28.809,52.254 ccw(c28.809,51.746) 28.301,51.746 28.301,49.911
NetC11_1 on Inner Layer 2 "Inner Layer 1-No Net" (solid, remove dead copper, pour order 37): 42.017,45.72 42.017,69.342 32.492,69.342 32.492,69.215 30.46,67.183 30.46,52.324 29.825,51.689 28.936,50.8 29.063,50.673 29.063,45.719
GND on Inner Layer 2 "Bottom Layer-gnd" (solid, remove dead copper, pour order 29): 7.219,44.958 37.445,44.958 37.445,4.826 7.219,4.826
GND on Bottom Layer "Bottom Layer-gnd" (solid, remove dead copper, pour order 28): 7.219,44.958 37.445,44.958 37.445,4.826 7.219,4.826
NetC10_2 on Bottom Layer "Top Layer-No Net 2" (solid, remove dead copper, pour order 32): 28.301,47.625 cw(c28.174,47.625) 28.174,47.498 27.92,47.498 27.286,47.498 ccw(c27.286,46.99) 26.778,46.99 26.778,45.953 cw(c26.281,45.953) 26.281,45.456 21.58,45.456 cw(c21.58,45.72) 21.316,45.72 21.316,46.609 ccw(c19.919,46.609) 19.919,48.006 15.775,48.006 15.706,48.006 cw(c15.706,49.391) 14.321,49.391 14.321,50.804 cw(c14.69,50.804) 14.69,51.174 19.567,51.174 ccw(c19.567,52.672) 21.066,52.672 21.066,68.584 cw(c21.443,68.584) 21.443,68.961 23.983,68.961 24.745,68.961 ccw(c24.745,69.723) 25.507,69.723 25.507,74.619 cw(c26.142,74.619) 26.142,75.254 37.121,75.254 cw(c37.121,72.771) 39.604,72.771 39.604,72.39 cw(c37.064,72.39) 37.064,69.85 36.937,69.85 32.365,69.85 ccw(c32.365,67.31) 29.825,67.31 29.825,52.832 cw(c29.247,52.832) 29.247,52.254 28.809,52.254 ccw(c28.809,51.746) 28.301,51.746 28.301,49.911
NetC11_1 on Bottom Layer "Inner Layer 1-No Net" (solid, remove dead copper, pour order 36): 42.017,45.72 42.017,69.342 32.492,69.342 32.492,69.215 30.46,67.183 30.46,52.324 29.825,51.689 28.936,50.8 29.063,50.673 29.063,45.719
NetC16_1 on Bottom Layer "Top Layer-vout" (solid, remove dead copper, pour order 25): 19.03,60.452 13.823,60.452 5.06,51.689 5.06,24.638 13.696,24.638 13.696,42.418 13.696,44.45 13.696,51.816 14.458,52.578 20.3,52.578 20.427,52.705 20.427,59.055

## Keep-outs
Keep-Out Layer:
  lines w0.254: -0.127,0 ccw(c0,0) 0,-0.127 cw(c0,0) -0.127,0
  text ".Layer_Name" at 14.656,-21.806 h1.52

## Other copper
Top Layer:
  text ".Layer_Name" at 14.656,-21.806 h1.52
Bottom Layer:
  text ".Layer_Name" at 14.656,-21.806 h1.52

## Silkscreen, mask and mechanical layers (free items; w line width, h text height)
Top Overlay:
  lines w0.254: 10.775,75.057 10.775,31.242 34.29,31.242 ; 10.775,75.184 34.397,75.184 ; 34.27,75.057 34.397,31.242
  text "PwrG" at 1.524,36.576 h1.02 r90
  text "GND" at 43.561,33.655 h1.02 r90
  text "NWA" at 1.524,30.988 h1.02 r90
  text "VOUT" at 1.524,25.4 h1.02 r90
  text ".PCB_Rev" at 40.874,22.606 h1.52 r90
  text "VOUT" at 10.902,20.193 h1.02
  text "GND" at 16.363,20.193 h1.02
  text ".PRJ_Number" at 40.874,7.366 h1.52 r90
  text "GND" at 20.681,2.413 h1.02
  text "VIN" at 34.524,2.413 h1.02
  text ".Layer_Name" at 14.656,-21.806 h1.52
Bottom Overlay:
  text ".Layer_Name" at 14.656,-21.806 h1.52
Top Paste:
  text ".Layer_Name" at 14.656,-21.806 h1.52
Bottom Paste:
  text ".Layer_Name" at 14.656,-21.806 h1.52
Top Solder:
  text ".Layer_Name" at 14.656,-21.806 h1.52
  text ".Layer_Name" at 14.656,-21.806 h1.52
Bottom Solder:
  text ".Layer_Name" at 14.656,-21.806 h1.52
Drill Guide:
  text ".Layer_Name" at 14.656,-21.806 h1.52
M1 Board Outline:
  the board outline again, w0.254
  text ".Layer_Name" at 14.656,-21.806 h1.52
M2 Board Dimensions:
  rectangle: 0,-6.985 3.175,-3.81
  rectangle: 3.175,-10.16 12.7,-6.985
  lines w0.178: 0,-6.985 25.4,-6.985 ; 3.175,-10.16 3.175,-3.81 ; 6.35,-10.16 6.35,-3.81 ; 12.7,-10.16 12.7,-3.81 ; 19.05,-10.16 19.05,-3.81 ; 0,-10.16 25.4,-10.16 25.4,-3.81 0,-3.81 0,-10.16
  text ".Layer_Name" at 14.656,-21.806 h1.52
M3 3D STEP Top:
  text ".Layer_Name" at 14.656,-21.806 h1.52
M4 3D STEP Bottom:
  text ".Layer_Name" at 14.656,-21.806 h1.52
M5 Assembly Top:
  lines w0.254: -7.417,-23.626 160.223,-23.626 ; -7.417,-18.462 160.274,-18.462 ; -7.417,-13.297 -7.417,-28.791 94.31,-28.791 160.274,-28.791 160.274,-13.297 -7.404,-13.297 -7.404,-28.791 32.614,-28.791 ; 55.194,-28.791 55.194,-13.297 ; 87.376,-18.462 87.376,-13.297 ; 108.712,-18.462 108.712,-13.297 ; 124.511,-28.956 124.511,-23.804
  text "COMPONENTS MARKED 'DNP' SHOULD NOT BE POPULATED." at 29.299,-8.09 h1.52
  text "ASSEMBLY VARIANT:" at 29.286,-11.024 h1.52
  text ".VariantName" at 55.601,-11.024 h1.52
  text "PCB VIEWED FROM TOP SIDE" at -5.804,-16.654 h1.52
  text "BOARD #:" at 57.099,-16.654 h1.52
  text ".PRJ_Number" at 70.955,-16.654 h1.52
  text "REV:" at 92.405,-16.654 h1.52
  text ".PCB_Rev" at 99.809,-16.654 h1.52
  text "SVN REV:" at 113.69,-16.654 h1.52
  text ".VersionControl_RevNumber" at 126.543,-16.654 h1.52
  text "PLOT NAME =" at -5.804,-27.034 h1.52
  text ".plot_File_Name" at 14.656,-27.034 h1.52
  text "GENERATED    :" at 57.15,-27.034 h1.52
  text ".Print_Date" at 79.235,-27.034 h1.52
  text ".Print_Time" at 97.752,-27.034 h1.52
  text "TEXAS INSTRUMENTS" at 129.87,-27.034 h1.52
M6 Assembly Bottom:
  lines w0.254: -7.429,-18.474 160.261,-18.474 ; -7.379,-23.639 160.261,-23.639 ; 28.334,-28.969 28.334,-23.817 ; 44.133,-18.474 44.133,-13.31 ; 65.468,-18.474 65.468,-13.31 ; 97.65,-28.804 97.65,-13.31 ; 120.231,-28.804 160.249,-28.804 160.249,-13.31 -7.429,-13.31 -7.429,-28.804 58.534,-28.804 160.261,-28.804 160.261,-13.31
  text "COMPONENTS MARKED 'DNP' SHOULD NOT BE POPULATED." at 154.991,-8.077 h1.52
  text ".VariantName" at 128.473,-11.024 h1.52
  text "ASSEMBLY VARIANT:" at 154.864,-11.024 h1.52
  text ".VersionControl_RevNumber" at 26.302,-16.667 h1.52
  text "SVN REV:" at 39.154,-16.667 h1.52
  text ".PCB_Rev" at 53.035,-16.667 h1.52
  text "REV:" at 60.439,-16.667 h1.52
  text ".PRJ_Number" at 81.89,-16.667 h1.52
  text "BOARD #:" at 95.745,-16.667 h1.52
  text "PCB VIEWED FROM BOTTOM SIDE" at 158.648,-16.667 h1.52
  text "TEXAS INSTRUMENTS" at 22.974,-27.047 h1.52
  text ".Print_Time" at 55.093,-27.047 h1.52
  text ".Print_Date" at 73.609,-27.047 h1.52
  text "GENERATED    :" at 95.694,-27.047 h1.52
  text ".plot_File_Name" at 138.189,-27.047 h1.52
  text "PLOT NAME =" at 158.648,-27.047 h1.52
M9 Title Sheet:
  drawing of 57 lines, arcs and shapes, not listed
  text "1" at 18.792,204.127 h1.78
  text "2" at 82.182,204.127 h1.78
  text "3" at 145.411,204.127 h1.78
  text "4" at 209.08,204.127 h1.78
  text "5" at 272.555,204.127 h1.78
  text "6" at 336.182,204.127 h1.78
  text "A" at -10.579,175.095 h1.78
  text "A" at 365.341,175.095 h1.78
  text "B" at -10.579,114.643 h1.78
  text "B" at 365.341,114.643 h1.78
  text "C" at -10.579,54.318 h1.78
  text "C" at 365.341,54.318 h1.78
  text "PROJECT TITLE:" at 288.125,7.048 h1.14
  text ".PRJ_Title" at 289.395,3.662 h1.78
  text "DESIGNED FOR:" at 288.125,-0.597 h1.14
  text ".PRJ_Customer" at 289.395,-4.153 h1.78
  text "D" at -10.579,-5.88 h1.78
  text "D" at 365.341,-5.88 h1.78
  text "FILE NAME:" at 288.125,-8.217 h1.14
  text ".PCB_File_Name_No_Path" at 289.395,-11.265 h1.78
  text "Texas Instruments (TI) and/or its licensors do not warrant the accuracy or completeness of this specification" at 161.9,-15.376 h1.14
  text "ENGINEER:" at 288.125,-15.583 h1.14
  text "LAYOUT BY:" at 326.352,-15.583 h1.14
  text "or any information contained therein. TI and/or its licensors do not warrant that this design will meet" at 160.757,-18.237 h1.14
  text ".PRJ_Engineer" at 289.395,-19.52 h1.78
  text ".PCB_Layout" at 327.635,-19.52 h1.78
  text "the specifications, will be suitable for your application or fit for any particular purpose, or will operate in" at 160.757,-21.099 h1.14
  text ".Layer_Name" at 14.656,-21.806 h1.52
  text "ALTIUM DESIGNER VERSION:" at 326.352,-23.457 h1.14
  text "an implementation. TI and/or its licensors do not warrant that the design is production worthy. You should" at 160.757,-23.961 h1.14
  text "completely validate and test your design implementation to confirm the system functionality for your application." at 161.9,-26.822 h1.14
  text ".print_Scale" at 289.395,-26.843 h1.78
  text ".Application_BuildNumber" at 327.635,-26.843 h1.78
  text "1" at 18.792,-32.093 h1.78
  text "2" at 82.182,-32.093 h1.78
  text "3" at 145.411,-32.093 h1.78
  text "4" at 209.08,-32.093 h1.78
  text "5" at 272.555,-32.093 h1.78
  text "6" at 336.182,-32.093 h1.78
M10 Fab Notes:
  drawing of 185 lines, arcs and shapes, not listed
  text "DESIGN INFORMATION" at 314.478,150.114 h1.52
  text "MIN. TRACK WIDTH:" at 298.106,145.542 h1.52
  text "8" at 325.951,145.542 h1.52
  text "MIL" at 329.881,145.542 h1.52
  text "MIN. CLEARANCE:" at 298.106,142.189 h1.52
  text "0.2" at 324.427,142.189 h1.52
  text "mm" at 329.881,142.189 h1.52
  text "MIN. VIA PAD SIZE:" at 298.106,138.836 h1.52
  text "24" at 325.189,138.836 h1.52
  text "MIL" at 329.881,138.836 h1.52
  text "0.05mm (2MIL)" at 315.759,135.237 h1.52
  text "MINIMUM ANNULAR RING" at 289.744,135.128 h1.52
  text "EXTERNAL" at 333.742,135.128 h1.52
  text "PER" at 294.824,132.131 h1.52
  text "IPC-D-275 CLASS 2 LEVEL C" at 300.412,132.131 h1.52
  text "MIL, HOLES" at 338.213,129.279 h1.52
  text "+/-" at 328.244,129.261 h1.52
  text "+/-" at 349.936,129.261 h1.52
  text "REGISTRATION TOLERANCES:" at 289.744,129.134 h1.52
  text "METAL" at 320.218,129.134 h1.52
  text "5" at 334.853,129.134 h1.52
  text "3" at 356.012,129.134 h1.52
  text "MIL" at 358.964,129.134 h1.52
  text "MATERIAL:" at 287.844,123.813 h1.52
  text "FR-4 High Tg" at 312.9,120.249 h1.52
  text "FR-408" at 298.538,120.031 h1.52
  text "X" at 309.003,120.031 h1.52
  text "OTHER" at 336.333,120.031 h1.52
  text "62 MIL (1.6mm) +/-10%" at 306.668,115.898 h1.52
  text "THICKNESS:" at 289.744,115.789 h1.52
  text "X" at 303.413,115.789 h1.52
  text "OTHER" at 339.305,115.789 h1.52
  text "TOLERANCE:" at 289.744,111.776 h1.52
  text "X" at 311.062,111.776 h1.52
  text "ANSI IPC-6012 TYPE 3 CLASS 2" at 315.81,111.776 h1.52
  text "OTHER +/-" at 315.81,107.814 h1.52
  text "BOW & TWIST:" at 289.744,103.826 h1.52
  text "X" at 311.062,103.826 h1.52
  text "ANSI IPC-6012 TYPE 3 CLASS 2" at 315.81,103.826 h1.52
  text "OTHER +/-" at 315.81,99.8 h1.52
  text "DRILLING:" at 287.844,96.282 h1.52
  text "REFERENCE:" at 289.744,93.31 h1.52
  text "X" at 306.209,93.31 h1.52
  text "AS SHOWN" at 310.958,93.31 h1.52
  text "X" at 329.094,93.31 h1.52
  text "NC_DRILL FILES" at 332.574,93.31 h1.52
  text "PTH MIN COPPER THICKNESS:" at 289.744,89.297 h1.52
  text "X" at 324.039,89.297 h1.52
  text "1MIL" at 327.519,89.297 h1.52
  text "OTHER" at 340.143,89.297 h1.52
  text "BOARD FINISH:" at 287.844,85.259 h1.52
  text "SILKSCREEN:" at 291.787,82.261 h1.52
  text "X" at 315.886,82.261 h1.52
  text "TOP" at 319.086,82.261 h1.52
  text "X" at 328.84,82.261 h1.52
  text "BOTTOM" at 332.066,82.261 h1.52
  text "SILKSCREEN COLOR:" at 291.787,78.02 h1.52
  text "X" at 315.86,78.02 h1.52
  text "WHITE" at 319.086,78.02 h1.52
  text "OTHER" at 332.066,78.02 h1.52
  text "SOLDER RESIST COLOR:" at 291.787,73.702 h1.52
  text "X" at 306.208,69.658 h1.52
  text "GREEN" at 309.434,69.658 h1.52
  text "BLUE" at 324.446,69.658 h1.52
  text "OTHER" at 338.111,69.658 h1.52
  text "IMMERSION GOLD (ENIG)" at 314.794,64.87 h1.52
  text "ENEPIG" at 348.767,64.786 h1.52
  text "SURFACE FINISH:" at 287.844,64.761 h1.52
  text "X" at 310.045,64.761 h1.52
  text "IMM. TIN/SILVER OR EQUIV" at 296.215,60.773 h1.52
  text "OTHER" at 332.574,60.773 h1.52
  text "ARRAY/PANEL:" at 287.844,56.226 h1.52
  text "CUT AND TRIM PER MECH LAYER 1" at 314.794,56.118 h1.52
  text "N.C. ROUTE" at 314.794,52.264 h1.52
  text "X" at 332.04,52.264 h1.52
  text "V. SCORE" at 336.79,52.264 h1.52
  text "CERTIFICATION:" at 287.844,48.784 h1.52
  text "MATERIALS AND WORKMANSHIP FOR ALL PCBS" at 306.259,48.784 h1.52
  text "TO MEET OR EXCEED THE REQUIREMENTS OF:" at 306.259,46.295 h1.52
  text "X" at 296.773,42.828 h1.52
  text "ANSI IPC-A-600F CLASS ->" at 300.303,42.828 h1.52
  text "X" at 341.935,42.828 h1.52
  text "2" at 344.956,42.828 h1.52
  text "1" at 336.955,42.79 h1.52
  text "3" at 353.948,42.79 h1.52
  text "X" at 296.825,38.777 h1.52
  text "UL 94V-0" at 300.303,38.777 h1.52
  text "X" at 317.45,38.777 h1.52
  text "RoHS" at 320.928,38.777 h1.52
  text "OTHER" at 337.296,38.777 h1.52
  text "PER ORDER" at 347.381,38.777 h1.52
  text "ADDITIONAL REQUIREMENTS:" at 287.844,35.195 h1.52
  text "MICROSECTION:" at 289.744,32.274 h1.52
  text "YES" at 312.749,32.274 h1.52
  text "REQUIRED" at 334.631,28.308 h1.52
  text "BARE BOARD ELEC. TEST:" at 289.744,28.236 h1.52
  text "NONE" at 322.909,28.236 h1.52
  text "X" at 331.405,28.236 h1.52
  text "PER ORDER" at 349.668,28.236 h1.52
  text "MANUFACTURER'S UL:" at 289.744,24.248 h1.52
  text "RAIL" at 319.353,24.139 h1.52
  text "METAL" at 331.845,24.139 h1.52
  text "X" at 341.376,24.13 h1.52
  text "SILK" at 344.842,24.139 h1.52
  text ".Layer_Name" at 14.656,-21.806 h1.52
M11 Gerber Information:
  lines w0.254: -7.417,-23.626 160.223,-23.626 ; -7.417,-18.462 160.274,-18.462 ; -7.417,-13.297 -7.417,-28.791 94.31,-28.791 160.274,-28.791 160.274,-13.297 -7.404,-13.297 -7.404,-28.791 32.614,-28.791 ; 55.194,-28.791 55.194,-13.297 ; 87.376,-18.462 87.376,-13.297 ; 108.712,-18.462 108.712,-13.297 ; 124.511,-28.956 124.511,-23.804
  text "ALL ARTWORK VIEWED FROM TOP SIDE" at -5.804,-16.654 h1.52
  text "BOARD #:" at 57.099,-16.654 h1.52
  text ".PRJ_Number" at 70.955,-16.654 h1.52
  text "REV:" at 92.405,-16.654 h1.52
  text ".PCB_Rev" at 99.809,-16.654 h1.52
  text "SVN REV:" at 113.69,-16.654 h1.52
  text ".VersionControl_RevNumber" at 126.543,-16.654 h1.52
  text "LAYER NAME =" at -5.804,-21.806 h1.52
  text "PLOT NAME =" at -5.804,-27.034 h1.52
  text ".plot_File_Name" at 14.656,-27.034 h1.52
  text "GENERATED    :" at 57.15,-27.034 h1.52
  text ".Print_Date" at 79.235,-27.034 h1.52
  text ".Print_Time" at 97.752,-27.034 h1.52
  text "TEXAS INSTRUMENTS" at 129.87,-27.034 h1.52
M12 Stackup:
  drawing of 191 lines, arcs and shapes, not listed
  text "Layer" at 248.681,198.882 h1.52
  text "Name" at 259.092,198.882 h1.52
  text "Material" at 282.708,198.882 h1.52
  text "Thickness" at 304.546,198.882 h1.52
  text "Constant" at 321.052,198.882 h1.52
  text "Board Layer Stack" at 335.526,198.882 h1.52
  text "1" at 248.681,195.834 h1.52
  text "Top Overlay" at 259.092,195.834 h1.52
  text "2" at 248.681,192.786 h1.52
  text "Top Solder" at 259.092,192.786 h1.52
  text "Solder Resist" at 282.708,192.786 h1.52
  text "0.40mil" at 304.546,192.786 h1.52
  text "3.5" at 321.052,192.786 h1.52
  text "3" at 248.681,189.738 h1.52
  text "Top Layer" at 259.092,189.738 h1.52
  text "Copper" at 282.708,189.738 h1.52
  text "1.40mil" at 304.546,189.738 h1.52
  text "4" at 248.681,186.69 h1.52
  text "Dielectric1" at 259.092,186.69 h1.52
  text "FR-4" at 282.708,186.69 h1.52
  text "59.20mil" at 304.546,186.69 h1.52
  text "4.8" at 321.052,186.69 h1.52
  text "5" at 248.681,183.642 h1.52
  text "Bottom Layer" at 259.092,183.642 h1.52
  text "Copper" at 282.708,183.642 h1.52
  text "1.40mil" at 304.546,183.642 h1.52
  text "6" at 248.681,180.594 h1.52
  text "Bottom Solder" at 259.092,180.594 h1.52
  text "Solder Resist" at 282.708,180.594 h1.52
  text "0.40mil" at 304.546,180.594 h1.52
  text "3.5" at 321.052,180.594 h1.52
  text "7" at 248.681,177.546 h1.52
  text "Bottom Overlay" at 259.092,177.546 h1.52
  text ".Layer_Name" at 14.656,-21.806 h1.52
M13 Component Bodies Top:
  text ".Layer_Name" at 14.656,-21.806 h1.52
M14 Component Bodies Bottom:
  text ".Layer_Name" at 14.656,-21.806 h1.52
M15 Courtyards Top:
  text ".Layer_Name" at 14.656,-21.806 h1.52
M16 Courtyards Bottom:
  text ".Layer_Name" at 14.656,-21.806 h1.52
Drill Drawing:
  lines w0.254: 140.917,65.985 141.55,66.302 142.183,65.985 141.866,66.618 142.183,67.251 141.55,66.935 140.917,67.251 141.233,66.618 140.917,65.985 ; 140.917,70.099 141.233,70.099 141.55,69.783 141.866,70.099 142.183,70.099 141.866,70.416 142.183,70.732 141.866,70.732 141.55,71.048 141.233,70.732 140.917,70.732 141.233,70.416 140.917,70.099 ; 140.917,74.846 142.183,74.846 141.55,73.58 140.917,74.846 ; 140.917,77.377 140.917,77.694 141.233,78.01 140.917,78.327 140.917,78.643 141.233,78.643 141.55,78.327 141.866,78.643 142.183,78.643 142.183,78.327 141.866,78.01 142.183,77.694 142.183,77.377 141.866,77.377 141.55,77.694 141.233,77.377 140.917,77.377 ; 140.917,81.491 141.233,81.491 141.233,81.175 141.866,81.175 141.866,81.491 142.183,81.491 142.183,82.124 141.866,82.124 141.866,82.44 141.233,82.44 141.233,82.124 140.917,82.124 140.917,81.491
  lines w0.305: 139.192,64.846 193,64.846 ; 139.192,83.833 193,83.833 ; 148.603,61.049 148.603,87.63 ; 157.675,61.049 157.675,87.63 ; 174.476,61.049 174.476,87.63 ; 181.695,61.049 181.695,87.63 ; 139.192,61.049 193,61.049 193,87.63 139.192,87.63 139.192,61.049
  text "Symbol" at 141.47,84.972 h1.83
  text "Quantity" at 149.742,84.972 h1.83
  text "Finished Hole Size" at 158.814,84.972 h1.83
  text "Plated" at 175.616,84.972 h1.83
  text "Hole Type" at 182.834,84.972 h1.83
  text "16" at 149.742,81.175 h1.52
  text "0.300mm (11.81mil)" at 158.814,81.175 h1.52
  text "PTH" at 175.616,81.175 h1.52
  text "Round" at 182.834,81.175 h1.52
  text "94" at 149.742,77.377 h1.52
  text "0.500mm (19.69mil)" at 158.814,77.377 h1.52
  text "PTH" at 175.616,77.377 h1.52
  text "Round" at 182.834,77.377 h1.52
  text "8" at 149.742,73.58 h1.52
  text "1.016mm (40.00mil)" at 158.814,73.58 h1.52
  text "PTH" at 175.616,73.58 h1.52
  text "Round" at 182.834,73.58 h1.52
  text "2" at 149.742,69.783 h1.52
  text "1.270mm (50.00mil)" at 158.814,69.783 h1.52
  text "PTH" at 175.616,69.783 h1.52
  text "Round" at 182.834,69.783 h1.52
  text "2" at 149.742,65.985 h1.52
  text "1.321mm (52.00mil)" at 158.814,65.985 h1.52
  text "PTH" at 175.616,65.985 h1.52
  text "Round" at 182.834,65.985 h1.52
  text "122 Total" at 149.742,62.188 h1.52
  text ".Layer_Name" at 14.656,-21.806 h1.52

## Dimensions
0,-10.16 to 25.4,-10.16 on M2 Board Dimensions
0,0 to 0,78.74 on M2 Board Dimensions
34.397,31.242 to 10.775,75.692 on Top Overlay
44.45,0 to 0,0 on M2 Board Dimensions
10.775,75.184 to 10.775,31.242 on Top Overlay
